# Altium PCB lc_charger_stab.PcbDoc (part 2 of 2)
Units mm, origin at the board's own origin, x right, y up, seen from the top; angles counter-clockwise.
Board outline 145 x 80 mm, 2 copper layers (Top Layer, Bottom Layer), stack 1.562 mm thick; 160 components, 79 nets, 423 pads, 71 vias.
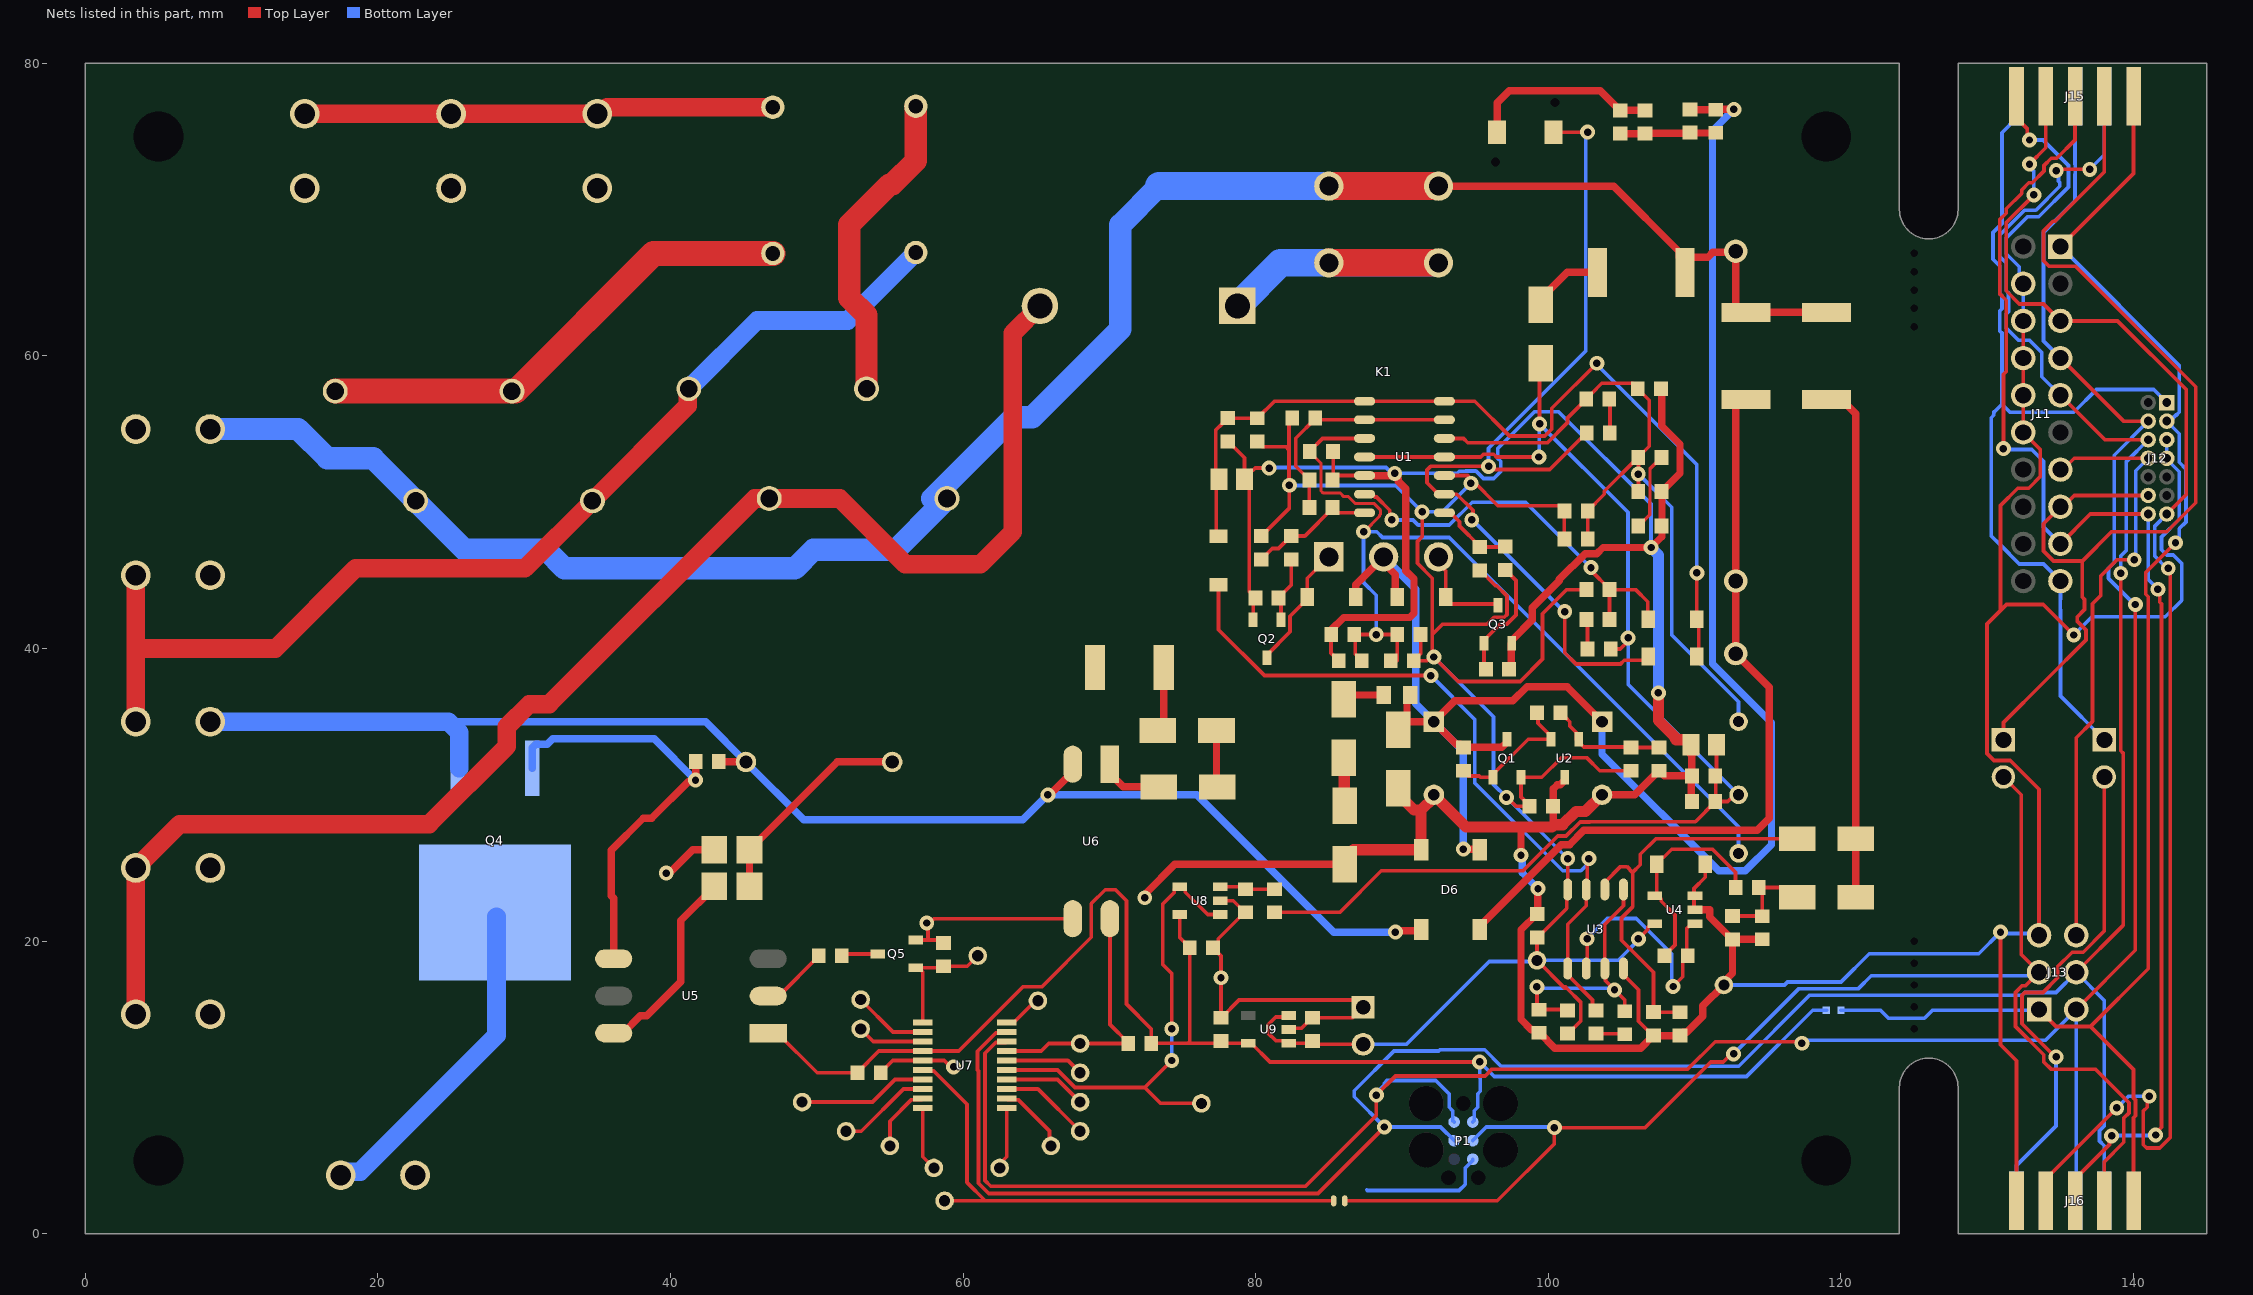
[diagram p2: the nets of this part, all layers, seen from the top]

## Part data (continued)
U9: library part CMP-ICPWR-00007-3, "200mA positive 18VIN 3.3Vout SOT-23-5 Linear Voltage Regulators (LDO) ROHS", Case/Package=SOT-23-5, Max Supply Voltage=18V, Output Current=200mA, Output Voltage=3.3V
Z1 Z6 Z7: library part CMP-NOBOM-00000-13, "Fiducial 1 mm copper, 3 mm solder mask, two footprint options."

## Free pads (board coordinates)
  round 0 hole 0.508 unplated paste-2539.97 mask+0: 2(125,14) 4(125,15.5) 5(125,17) 7(125,20) 8(125,18.5) 9(125,67) 10(125,65.75) 11(125,64.5) 12(125,63.25) 13(125,62)

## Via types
v1: diameter 1.016, hole 0.508, Top Layer to Bottom Layer, tented both sides, 70 vias
v2: diameter 1.6, hole 1, Top Layer to Bottom Layer, 1 vias

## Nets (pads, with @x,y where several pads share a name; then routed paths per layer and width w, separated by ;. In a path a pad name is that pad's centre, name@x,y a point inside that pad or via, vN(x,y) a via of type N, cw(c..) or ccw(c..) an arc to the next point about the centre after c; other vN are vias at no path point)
3V3: C3.1 C4.1 C9.1 NT1.2 P1.1 R30.1 U5.1 U7.4 U8.5 U9.5 | length 105.5
  Top Layer w0.254: U5.1@46.68,13.71 47.315,13.71 50.025,11 C4.1@52.774,11 52.774,11.025 54.239,12.49 U7.4@57.239,12.49 59.702,12.49 64.094,16.882 65.386,16.882 68.765,20.26 68.765,22.562 69.713,23.51 70.417,23.51 71.165,22.762 71.165,15.7 72.865,14 R30.1@72.865,13.012 75.34,13.012 ; U8.5@74.813,21.812 74.813,20.243 75.488,19.568 C3.1@75.488,19.543 75.488,13.16 75.34,13.012 ; v1(95.304,11.741) 80.972,11.741 79.701,13.012 U9.5@79.501,13.012 77.777,13.012 C9.1@77.627,13.162 77.477,13.012 75.34,13.012
  Bottom Layer w0.254: P1.1@94.831,7.635 94.935,7.739 94.935,8.411 95.171,8.647 95.171,9.553 95.352,9.734 95.352,10.615 95.304,10.663 v1(95.304,11.741) 96.295,10.75 113.545,10.75 118.07,15.275 NT1.2@119.007,15.275
5Vprobe: J11.19 J12.1 J15.1 J17.1 | length 62
  Bottom Layer w0.254: 130.445,55.953 130.269,55.777 130.269,47.696 130.898,47.067 132.192,45.773 133.835,45.773 J11.19@135,44.608 135,43.376 134.978,43.354 134.978,42.662 135,42.64 135,36.759 J17.1@138,33.759 ; 130.445,55.957 130.463,56.157 130.537,56.231 131,56.694 ; J15.1@132,77.75 132,76.25 131,75.25 131,69.046 130.39,68.436 130.39,66.611 130.844,66.157 130.844,64.259 131,64.103 131,63.213 130.844,63.057 130.844,61.719 131,61.563 131,56.694 ; J12.1@142.27,56.81 141.385,57.695 137.456,57.695 135.907,56.146 131.548,56.146 131,56.694
5Vtarget: J16.1 J17.2 | length 34.6
  Top Layer w0.254: v1(134.7,12.087) 134.647,12.087 132.376,14.357 132.376,16.298 132.568,16.49 133.803,16.49 134.808,17.494 134.808,18.241 135.813,19.246 136.559,19.246 138,20.686 J17.2@138,31.219
  Bottom Layer w0.254: J16.1@132,2.25 132,4.669 134.7,7.369 v1(134.7,12.087)
ac_sense: SNS.1 U7.15 U8.1 U8.4 | length 33.2
  Top Layer w0.254: U7.15@62.989,11.19 66.45,11.19 67.64,10 72.416,10 ; v1(74.256,11.84) 72.416,10 ; v1(74.256,14) 74.256,17.791 73.64,18.407 73.64,22.539 74.44,23.339 74.44,23.539 74.613,23.712 U8.4@74.813,23.712 75.013,23.712 75.186,23.539 75.186,23.339 76.713,21.812 U8.1@77.563,21.812 ; SNS.1@76.288,8.909 73.507,8.909 72.416,10
  Bottom Layer w0.254: v1(74.256,11.84) v1(74.256,14)
diffp: R36.2 R37.1 U8.3 | length 3.8
  Top Layer w0.254: U8.3@77.563,23.712 79.128,23.712 R37.1@79.288,23.552 R36.2@81.288,23.552
gate: Q4.G R33.1 U5.4 | length 30.5
  Top Layer w0.508: U5.4@36.12,18.79 36.12,22.92 35.948,23.092 35.948,26.208 38.152,28.412 38.73,28.412 41.221,30.903 41.612,30.903 v1(41.709,31) 41.714,31.005 41.714,32.272 R33.1@41.719,32.277
  Bottom Layer w0.508: Q4.G@30.54,31.815 30.54,33.215 30.786,33.461 31.584,33.461 31.952,33.829 38.88,33.829 v1(41.709,31)
GND: GDT2.2 J7.1 J7.2 J8.1 J8.2 J9.1 J9.2 | length 32.2
  Top Layer w1.27: J8.1@15,76.54 J7.1@25,76.54 J9.1@35,76.54 35.206,76.54 35.666,77 GDT2.2@47,77
GND_PROT: C1.2 C3.2 C4.2 C8.2 C9.2 C12.2 C15.2 C16.2 C25.2 C119.2 C120.2 C121.2 C122.2 C123.2 C124.- C125.- D6.- D8.A D20.A D22.A J10.1 J11.4 J11.6 J11.8 J11.10 J11.12 J12.5 J12.7 J13.5 J15.6 J16.6 P1.5 Q2.2 Q3.2 Q5.2 R6.2 R9.2 R15.2 R17.1 R21.2 R24.1 R28.2 R31.2 R35.2 R37.2 R39.2 R44.2 R47.2 R64.2 TP12.1 U1.12 U2.3 U3.4 U4.2 U4.3 U6.3 U7.5 U8.2 U9.2 | length 409.4
  Top Layer w0.229: C120.2@107.673,57.749 C120.2@107.762,57.66
  Top Layer w0.254: C4.2@54.374,11 54.374,11.025 55.189,11.84 U7.5@57.239,11.84 58.708,11.84 59.143,11.405 v1(59.349,11.405) ; Q5.2@56.754,20.072 57.603,20.072 ; R35.2@58.657,19.867 58.451,20.072 57.603,20.072 ; U6.3@67.495,21.53 58.016,21.53 57.722,21.237 v1(57.516,21.237) 57.603,21.15 57.603,20.072 ; U8.2@77.563,22.762 78.458,22.762 R37.2@79.248,21.972 ; C9.2@77.627,14.762 v1@77.627,17.561 ; v1(77.627,17.5) v1@77.627,17.561 ; C9.2@77.652,14.762 78.861,15.972 86.854,15.972 J10.1@87.337,15.489 86.609,14.762 C8.2@83.876,14.762 83.851,14.762 83.132,14.043 82.332,14.043 U9.2@82.251,13.962 ; C122.2@78.098,54.145 78.123,54.145 79.229,53.04 C1.2@79.229,51.577 ; R37.2@79.288,21.972 R37.2@79.248,21.972 ; C1.2@79.306,51.81 79.682,52.185 79.837,52.185 79.982,52.33 v1(80.909,52.33) ; C1.2@79.562,51.04 79.562,43.893 79.822,43.632 Q2.2@79.822,41.654 ; R28.2@85.149,40.954 85.149,39.697 85.657,39.189 R31.2@85.657,39.164 ; R9.2@85.265,51.504 R9.2@85.293,51.531 ; C121.2@85.293,53.462 R9.2@85.293,51.531 ; U1.12@88.133,51.82 U1.12@87.44,51.82 85.581,51.82 R9.2@85.293,51.531 ; U3.4@105.133,18.124 105.133,17.694 106.157,16.67 106.157,14.526 C16.2@106.788,13.895 ; R15.2@107.767,50.408 R15.2@107.767,50.75 ; U4.2@109.951,22.144 109.951,23.593 110.725,24.367 D20.A@110.725,25.253 ; v1(130.901,20.619) 130.901,12.92 132,11.821 J16.6@132,2.25 ; J15.6@132,77.75 132,76.25 132.74,75.51 132.74,74.901 v1(132.886,74.755) ; J11.6@132.46,62.388 J11.8@132.46,59.848 J11.10@132.46,57.308 J11.12@132.46,54.768 133.622,53.606 133.622,51.747 132.833,50.958 132.087,50.958 130.901,49.773 130.901,42.593 ; J13.5@133.538,20.408 133.538,30.379 131.571,32.346 130.454,32.346 129.977,32.824 129.977,41.668 130.901,42.593 ; v1(135.907,40.921) 133.821,43.008 131.317,43.008 130.901,42.593 ; v1@77.627,17.561 77.627,18.98 77.088,19.518 C3.2@77.088,19.543 77.436,19.891 77.436,20.16 R37.2@79.248,21.972
  Top Layer w0.508: v1(72.416,22.962) 72.513,23.059 72.513,23.287 74.478,25.252 D8.A@86.087,25.252 ; R28.2@85.134,41.235 86.018,42.119 90.518,42.119 90.816,42.417 90.816,44.755 90.267,45.304 90.267,50.905 89.742,51.43 ; U1.12@88.133,51.82 89.52,51.82 v1@89.742,51.597 ; R24.1@97.325,38.579 97.455,38.71 97.455,40.315 97.547,40.407 97.547,40.607 98.896,41.956 98.896,42.772 100.751,44.626 100.751,44.723 102.514,46.487 103.316,46.487 103.734,46.904 v1(107.019,46.904) 107.767,47.652 R15.2@107.767,50.408 ; 97.98,27.799 98.133,27.646 v1(98.133,25.873) ; v1(99.291,23.593) 99.269,23.571 99.269,21.875 C25.2@99.247,21.853 99.222,21.853 98.133,20.763 98.133,14.653 98.834,13.952 99.158,13.952 R64.2@99.374,13.735 ; R64.2@99.399,13.726 100.435,12.69 106.303,12.69 107.161,13.547 C16.2@107.186,13.547 107.189,13.544 R47.2@109.005,13.544 ; 100.175,27.799 100.325,27.949 C119.2@100.325,29.225 100.325,30.4 100.622,30.698 100.822,30.698 101.125,31 U2.3@101.125,31.2 ; C124.-@103.669,30 105.894,30 107.534,31.64 107.584,31.64 107.929,31.295 R44.2@109.765,31.295 ; C120.2@107.762,57.66 107.762,55.209 108.999,53.972 108.999,51.982 R15.2@107.767,50.75 ; R47.2@109.008,13.551 109.224,13.767 109.458,13.767 110.561,14.87 110.561,15.572 112.014,17.025 112.014,17.231 112.588,17.806 C12.2@112.588,20.113 ; C15.2@109.765,29.617 R44.2@109.765,31.295 ; C123.2@109.791,32.899 R44.2@109.791,31.295 ; R44.2@109.816,31.295 R44.2@109.791,31.295 ; U4.2@109.951,22.144 U4.2@110.026,22.144 111.031,22.144 111.031,21.646 112.563,20.113 C12.2@112.588,20.113 ; R39.2@114.62,20.113 C12.2@112.588,20.113 ; R44.2@109.765,31.295 R44.2@109.791,31.295
  Top Layer w0.762: D8.A@86.087,25.252 86.087,25.652 86.684,26.249 D6.-@91.304,26.249 91.304,28.957 ; D22.A@89.743,30.44 89.743,30.04 90.826,28.957 91.304,28.957 ; C124.-@103.669,30 102.523,28.854 101.881,28.854 100.982,27.955 100.412,27.955 100.256,27.799 100.175,27.799 97.98,27.799 94.376,27.799 C125.-@92.175,30 92.175,29.827 91.304,28.957 ; v1(107.526,36.965) 107.526,35.07 108.651,33.945 108.651,33.844 108.731,33.763 109.542,33.763 109.741,33.564 C123.2@109.741,33.409 ; C123.2@109.791,32.899 C123.2@109.791,33.409
  Bottom Layer w0.254: v1@80.909,52.372 88.899,52.372 89.299,51.972 v1(89.505,51.972) 93.773,51.972 93.923,52.122 94.345,52.122 94.356,52.133 95.047,52.133 95.569,51.612 96.261,51.612 96.75,52.101 96.75,52.793 96.55,52.992 96.55,53.68 99.056,56.187 100.701,56.187 107.019,49.869 v1(107.019,46.904) ; 87.587,3 87.634,2.953 92.812,2.953 92.816,2.948 93.543,2.948 93.548,2.953 93.898,2.953 94.32,3.374 94.32,4.501 94.831,5.012 P1.5@94.831,5.095 ; TP12.1@112,17 116.136,17 116.342,17.206 120.008,17.206 121.933,19.131 129.414,19.131 v1(130.901,20.619) 131.007,20.513 133.433,20.513 J13.5@133.538,20.408 ; J11.6@132.46,62.388 J11.4@132.46,64.928 132.189,65.199 132.189,66.096 131.298,66.987 131.298,68.06 132.74,69.502 133.51,69.502 135.546,71.538 135.546,72.582 135.55,72.586 135.55,73.011 133.806,74.755 v1(132.886,74.755) ; v1(135.907,40.921) 137.151,42.165 142.169,42.165 143.292,43.289 143.292,45.803 142.707,46.388 142.267,46.388 141.908,46.747 141.908,47.616 143.127,48.835 143.127,52.085 142.27,52.942 J12.7@142.27,53 J12.5@142.27,54.27
  Bottom Layer w0.508: v1(98.133,25.873) 98.23,25.776 98.23,24.654 v1(99.291,23.593)
  Bottom Layer w0.762: v1(107.019,46.904) 107.526,46.397 v1(107.526,36.965)
heater_out: J2.1 J2.2 MECH2.1 Q4.OUT R22.2 | length 26.8
  Top Layer w0.508: v1(39.71,24.65) 39.807,24.747 40.026,24.747 41.529,26.25 R22.2@42.98,26.25
  Bottom Layer w1.27: J2.1@17.46,3.75 17.96,4.25 18.79,4.25 28.11,13.57 Q4.OUT@28.11,21.675
input_ok: C1.1 C122.1 D3.A D4.A D5.A R5.2 U1.7 U1.8 | length 61.7
  Top Layer w0.254: C1.1@77.302,51.577 77.302,47.82 D4.A@77.454,47.668 ; C1.1@77.479,51.577 77.272,51.785 77.272,54.927 77.726,55.381 77.726,55.397 78.074,55.745 R5.2@79.953,55.745 ; R5.2@80.105,55.745 80.13,55.745 81.284,56.9 U1.8@87.44,56.9 U1.7@92.565,56.9 ; U1.7@92.89,56.9 94.969,56.9 97.352,54.517 99.748,54.517 100.237,55.006 100.237,56.419 v1(103.319,59.5) ; D5.A@110.262,39.2 110.287,39.2 110.287,41.858 D3.A@110.151,41.994 v1(110.151,45.169) ; v1(110.151,45.169) 110.151,45.236 110.036,45.351 110.002,45.318 109.853,45.169 v1(110.151,45.169)
  Bottom Layer w0.254: v1(103.319,59.5) 103.319,59.39 110.151,52.558 v1(110.151,45.169)
L2: J1.1 J1.2 J3.1 J3.2 L2.2 R1.1 RV2.1 | length 100.3
  Top Layer w1.27: J1.2@3.46,15 J3.2@3.46,25 6.46,28 23.5,28 28.808,33.308 28.808,34.651 30.357,36.2 31.7,36.2 45.75,50.25 RV2.1@46.75,50.25 51.57,50.25 56.055,45.765 61.185,45.765 63.385,47.965 63.385,61.549 L2.2@65.25,63.414
  Bottom Layer w1.27: L2.2@65.25,63.373 L2.2@65.25,63.414 L2.2@65.25,63.499
LINE: C5.1 J4.1 J4.2 K1.NO1 K1.NO2 R2.1 R3.1 R10.1 RV1.2 RV3.1 | length 145.2
  Top Layer w0.508: K1.NO2@92.493,71.602 104.463,71.602 108.929,67.136 108.929,66.735 R3.1@109.325,66.339 ; R3.1@109.325,65.697 R3.1@109.325,66.339 ; R10.1@119,62.975 R2.1@113.5,62.975 113.205,62.975 112.809,63.371 C5.1@112.809,67.15 112.731,67.072 111.247,67.072 110.91,66.735 109.721,66.735 R3.1@109.325,66.339
  Top Layer w1.905: K1.NO1@84.993,71.602 K1.NO2@92.493,71.602
  Bottom Layer w1.524: J4.1@8.54,55 14.543,55 16.543,53 19.675,53 RV3.1@22.587,50.088 25.925,46.75 31.48,46.75 32.754,45.476 48.498,45.476 49.772,46.75 55.4,46.75 58.4,49.75 RV1.2@58.9,50.25 ; 57.9,50.25 58.4,50.75 63.461,55.811 64.735,55.811 70.75,61.826 70.75,68.956 73.396,71.602
  Bottom Layer w1.905: 73.396,71.602 K1.NO1@84.993,71.602 K1.NO2@92.493,71.602
LPROT: K1.COM1 K1.COM2 L2.1 | length 22.5
  Top Layer w1.905: K1.COM1@84.975,66.38 K1.COM1@84.993,66.362 K1.COM2@92.493,66.362
  Bottom Layer w1.905: L2.1@78.75,63.414 81.698,66.362 K1.COM1@84.993,66.362 K1.COM2@92.493,66.362
NC.MOV5: GDT2.1 RV3.2 RV4.2 | length 33.8
  Top Layer w1.7: RV3.2@17.087,57.588 29.424,57.588 38.836,67 GDT2.1@47,67
NetC2_1: C2.1 R14.2 R22.1 | length 14.8
  Top Layer w0.508: R14.2@45.4,23.75 R22.1@45.4,26.25 45.4,26.31 46.021,26.931 46.081,26.931 51.395,32.245 C2.1@55.155,32.245
NetC5_2: C5.2 D6.AC1 R2.2 | length 53.1
  Top Layer w0.508: D6.AC1@95.304,20.799 95.304,21.024 100.879,26.599 101.449,26.599 102.415,27.565 107.098,27.565 107.114,27.581 114.281,27.581 115.1,28.4 115.1,37.359 C5.2@112.809,39.65 v2(112.809,44.616) 112.809,56.629 113.205,57.025 R2.2@113.5,57.025
NetC6_2: C6.2 Q2.1 R17.2 | length 4.9
  Top Layer w0.254: Q2.1@81.722,41.654 81.722,43.307 81.572,43.457 81.572,43.482 82.421,44.331 C6.2@82.421,46.092 C6.2@82.446,46.092
NetC7_2: C7.2 Q3.1 R24.2 | length 8.3
  Top Layer w0.254: R24.2@95.725,38.579 95.601,38.703 Q3.1@95.601,40.361 95.601,40.561 96.72,41.68 97.175,41.68 97.787,42.292 97.787,44.646 97.438,44.995 97.438,45.02 97.09,45.368 C7.2@97.065,45.368
NetC118_1: C118.1 Q1.1 R20.1 U2.2 | length 9.6
  Top Layer w0.254: R20.1@94.196,31.64 94.544,31.292 95.264,31.292 95.356,31.2 Q1.1@96.225,31.2 96.225,31.4 98.624,33.8 U2.2@100.175,33.8 100.175,34 99.287,34.888 99.287,35.567 C118.1@99.234,35.62
NetC118_2: C118.2 R6.1 R13.2 U2.1 | length 8.2
  Top Layer w0.254: C118.2@100.834,35.62 100.834,35.595 101.182,35.247 101.207,35.247 101.456,34.997 101.456,34.707 101.902,34.261 101.902,33.773 102.415,33.26 105.631,33.26 105.652,33.24 R6.1@107.559,33.24
NetD7_A: D7.A R1.2 | length 4.5
  Top Layer w0.508: D7.A@73.316,34.4 73.715,34.799 R1.2@73.715,38.703
NetD7_K: D7.K D10.K | length 3.9
  Top Layer w0.508: D7.K@77.316,34.4 77.316,30.594 D10.K@77.365,30.545
NetD8_K: D8.K D9.A | length 3.3
  Top Layer w0.762: D9.A@86.013,32.524 86.05,32.487 86.05,29.289 D8.K@86.087,29.252
NetD9_K: D9.K R181.2 | length 2.9
  Top Layer w0.508: D9.K@86.013,36.524 86.311,36.821 R181.2@88.76,36.821
NetD10_A: D10.A U6.1 | length 4.3
  Top Layer w0.508: U6.1@70.035,32.09 70.035,31.455 70.945,30.545 D10.A@73.365,30.545
NetD20_K: D20.K R50.2 R59.1 U4.4 | length 15.2
  Top Layer w0.254: R59.1@107.643,18.708 107.935,19 107.935,19.025 108.651,19.74 108.651,21.319 108.651,21.794 107.724,22.721 107.724,22.871 107.501,23.094 107.351,23.094 107.405,23.148 D20.K@107.405,25.253 107.405,25.405 107.736,25.735 107.888,25.735 108.439,26.286 111.221,26.286 112.795,24.712 R50.2@112.795,23.669
NetD57_A: D57.A R3.2 | length 5
  Top Layer w0.254: D57.A@99.477,63.5 D57.A@99.477,63.9
  Top Layer w0.508: D57.A@99.477,63.9 101.295,65.718 R3.2@103.354,65.718
NetD58_A: D58.A D59.K R10.2 | length 35.5
  Top Layer w0.508: R10.2@119,57.025 120.025,57.025 120.421,56.629 121,56.05 D59.K@121,23
NetD60_A: D60.A R48.2 R49.2 | length 13
  Top Layer w0.508: D60.A@96.498,75.292 96.498,77.292 97.339,78.133 103.547,78.133 104.89,76.789 104.915,76.789 R49.2@106.6,76.789
NetGDT1_2: GDT1.2 RV1.1 | length 21.8
  Top Layer w1.524: RV1.1@53.4,57.75 53.4,62.782 52.21,63.972 52.21,68.956 54.97,71.716 55.15,71.716 56.772,73.338 GDT1.2@56.772,77.067
NetQ5_3: Q5.3 R34.2 | length 2.5
  Top Layer w0.254: R34.2@51.705,19 51.827,19.122 Q5.3@54.154,19.122
NetR4_1: R4.1 R8.1 | length 2.3
  Top Layer w0.254: R4.1@104.179,57.019 R4.1@104.179,57.044 ; R8.1@104.211,54.742 R4.1@104.211,57.044
NetR7_2: R7.2 R9.1 R12.1 U1.6 U1.9 | length 16
  Top Layer w0.254: R12.1@83.665,49.624 83.665,51.504 83.665,51.529 82.732,52.462 82.732,54.371 84.081,55.72 84.081,55.745 84.197,55.63 U1.6@92.959,55.63
NetR11_1: R11.1 R21.1 | length 5.2
  Top Layer w0.203: 106.936,50.067 106.936,51.547 106.956,51.567 106.956,52.283
  Top Layer w0.254: R21.1@106.167,48.376 106.936,49.145 106.936,50.067 ; 106.956,52.283 R11.1@107.622,52.948
NetR14_1: R14.1 U5.6 | length 13.5
  Top Layer w0.508: U5.6@36.12,13.71 36.755,13.71 37.946,14.901 38.366,14.901 40.7,17.235 40.7,21.41 42.98,23.69 R14.1@42.98,23.75
NetR26_1: R26.1 R27.2 | length 2.1
  Top Layer w0.254: R26.1@102.597,41.993 102.673,41.916 R27.2@102.673,39.961
NetR48_1: R48.1 R49.1 R52.2 R56.2 | length 6.6
  Top Layer w0.508: R48.1@104.915,75.189 106.6,75.189 106.631,75.22 109.649,75.22 R56.2@109.679,75.25 ; R56.2@109.68,75.235 R52.2@111.443,75.235
NetR54_1: R54.1 R58.1 | length 2.1
  Top Layer w0.254: R58.1@103.133,13.675 R58.1@103.189,13.619 ; R58.1@103.267,13.675 105.165,13.675 R54.1@105.221,13.619
NEUT: C2.2 D6.AC2 GDT1.1 J5.1 J5.2 J6.1 J6.2 Q4.COM R33.2 RV2.2 RV4.1 U6.2 | length 173.6
  Top Layer w0.508: R33.2@43.299,32.277 43.315,32.261 45.139,32.261 C2.2@45.155,32.245 ; v1(65.79,29.996) 65.913,29.996 67.495,31.578 U6.2@67.495,32.09 ; v1(89.542,20.619) 89.632,20.709 91.214,20.709 D6.AC2@91.304,20.799
  Top Layer w1.27: J5.2@3.46,35 3.46,40 ; J6.2@3.46,45 3.46,40 ; RV2.2@41.25,57.75 41.168,57.668 41.168,56.591 RV4.1@34.664,50.088 30.052,45.476 18.476,45.476 13,40 3.46,40
  Bottom Layer w0.508: 24.826,35 42.4,35 C2.2@45.155,32.245 49.109,28.291 64.086,28.291 v1(65.79,29.996) 75.96,29.996 85.337,20.619 v1(89.542,20.619)
  Bottom Layer w1.27: J5.1@8.54,35 24.826,35 25.57,34.256 Q4.COM@25.57,31.815 ; RV2.2@41.25,57.75 45.918,62.418 52.123,62.418 GDT1.1@56.772,67.067
NRST: J13.3 J14.2 J16.9 P1.3 SJ1.1 | length 97
  Top Layer w0.254: SJ1.1@86.087,2.25 96.512,2.25 100.412,6.15 v1(100.412,7.25) 106.614,7.25 111.105,11.741 111.952,11.741 112.5,12.289 v1(112.661,12.289) ; J14.2@131.104,31.219 132.314,30.009 132.314,19.092 J13.3@133.538,17.868 132.614,16.944 132.38,16.944 131.922,16.486 131.922,14.169 133.865,12.226 133.865,11.741 134.354,11.252 137.375,11.252 139.681,8.946 139.681,8.254 139.335,7.908 139.335,6.246 138,4.911 J16.9@138,2.25
  Bottom Layer w0.254: P1.3@94.831,6.365 95.76,7.295 100.367,7.295 v1(100.412,7.25) ; v1(112.661,12.289) 117.125,16.752 121.193,16.752 122.072,17.631 133.301,17.631 J13.3@133.538,17.868
NRST_MCU: NRST_MCU.1 SJ1.2 U7.6 | length 37.7
  Top Layer w0.254: U7.6@57.239,11.19 57.312,11.117 58,11.117 60.26,8.857 60.26,3.51 61.52,2.25 ; NRST_MCU.1@58.739,2.25 61.52,2.25 ; SJ1.2@85.325,2.25 61.52,2.25
NRST_PROBE: J11.15 J12.12 J14.1 J15.9 | length 72.2
  Top Layer w0.254: J14.1@131.104,33.759 131.104,34.94 133.921,37.758 133.925,37.758 136.742,40.576 136.742,41.267 136.159,41.851 136.159,42.173 136.648,42.662 136.648,43.354 136.5,43.502 136.5,45.986 ; J15.9@138,77.75 138,72.569 134.631,69.2 134.5,69.2 133.838,68.538 133.838,66.498 134.202,66.134 136.011,66.134 144.25,57.894 144.25,49.958 142.264,47.972 138.486,47.972 136.5,45.986 ; J12.12@141,50.46 135.948,50.46 135.176,49.688 J11.15@135,49.688 133.838,48.526 133.838,46.667 134.519,45.986 136.5,45.986
opto_k1: R34.1 U5.2 | length 4.6
  Top Layer w0.254: U5.2@46.68,16.25 47.415,16.25 50.125,18.96 R34.1@50.125,19
overvoltage#: D5.K D60.K R8.2 U1.2 | length 63.2
  Top Layer w0.254: U1.2@92.565,50.55 92.484,50.55 91.712,51.322 91.712,52.205 91.953,52.447 v1(95.915,52.447) 96.134,52.227 100.096,52.227 102.238,54.369 102.263,54.369 102.611,54.717 R8.2@102.611,54.742 ; U1.2@92.959,50.55 93.74,50.55 94.843,49.447 94.843,48.864 v1(94.768,48.788) ; D60.K@100.361,75.292 v1(102.679,75.292) ; v1(101.125,42.524) 101.125,39.708 101.887,38.946 104.935,38.946 105.189,39.2 106.812,39.2 D5.K@106.694,39.317
  Bottom Layer w0.254: v1(94.768,48.788) 94.814,48.788 101.078,42.524 v1(101.125,42.524) ; v1(95.915,52.447) 95.915,53.687 102.562,60.335 102.562,75.175 v1(102.679,75.292)
PA0: PA0.1 U7.7 | length 8.9
  Top Layer w0.254: PA0.1@49,9 53.811,9 55.351,10.54 U7.7@57.239,10.54
PA1: PA1.1 U7.8 | length 6.4
  Top Layer w0.254: PA1.1@52,7 53.038,7 55.928,9.89 U7.8@57.239,9.89
PA2: PA2.1 U7.9 | length 4.6
  Top Layer w0.254: PA2.1@55,6 55,7.688 56.479,9.167 57.166,9.167 U7.9@57.239,9.24
PA3: PA3.1 U7.10 | length 4.4
  Top Layer w0.254: U7.10@57.239,8.59 57.239,5.261 PA3.1@58,4.5
PA4: PA4.1 U7.11 | length 4.3
  Top Layer w0.254: PA4.1@62.5,4.5 62.5,4.775 62.989,5.264 U7.11@62.989,8.59
PA5: PA5.1 U7.12 | length 4.9
  Top Layer w0.254: U7.12@62.989,9.24 63.062,9.167 63.75,9.167 65.901,7.016 65.901,6.099 PA5.1@66,6
PA6: PA6.1 U7.13 | length 6.2
  Top Layer w0.254: U7.13@62.989,9.89 65.11,9.89 PA6.1@68,7
PA7: PA7.1 U7.14 | length 5.6
  Top Layer w0.254: U7.14@62.989,10.54 66.457,10.54 67.997,9 PA7.1@68,9
PA11: PA11.1 U7.16 | length 5.4
  Top Layer w0.254: U7.16@62.989,11.84 67.16,11.84 PA11.1@68,11
PB6: PB6.1 U7.20 | length 2.7
  Top Layer w0.254: U7.20@62.989,14.44 63.464,14.44 64.944,15.92 PB6.1@65.114,15.92
PC14: PC14.1 U7.2 | length 5.2
  Top Layer w0.254: PC14.1@53,16 55.21,13.79 U7.2@57.239,13.79
PC15: PC15.1 U7.3 | length 4.6
  Top Layer w0.254: PC15.1@53,14 53.86,13.14 U7.3@57.239,13.14
peak_neg: C12.1 D59.A R39.1 R50.1 | length 7
  Top Layer w0.254: C12.1@112.563,21.713 114.62,21.713 114.62,23.443 114.395,23.669 116.331,23.669 D59.A@117,23
peak_neg_inv: R59.2 U3.2 U4.1 | length 16.1
  Top Layer w0.254: v1(102.651,20.159) 102.655,20.155 102.655,18.009 U3.2@102.658,18.005 ; v1(108.524,16.898) 109.187,17.562 109.187,18.652 R59.2@109.535,19 ; R59.2@109.451,19.323 109.451,20.844 109.801,21.194 U4.1@109.951,21.194
  Bottom Layer w0.254: v1(102.651,20.159) 104.044,21.553 106.003,21.553 ; 106.02,21.534 108.248,19.307 108.439,19.116 v1@108.439,17.221
peak_out: D4.K R58.2 U3.1 U3.7 | length 49.1
  Top Layer w0.254: D4.K@77.454,44.348 77.454,41.288 80.592,38.15 v1(91.97,38.15) ; U3.1@101.323,18.424 101.323,21.154 102.593,22.424 U3.7@102.593,23.224 ; U3.1@101.388,18.005 101.436,17.957 101.436,17.561 103.015,15.982 103.015,15.527 R58.2@103.107,15.435 ; U3.7@102.593,23.524 102.659,23.59 102.659,25.529 v1(102.767,25.637)
  Bottom Layer w0.254: v1(91.97,38.15) 94.97,35.15 94.97,30.809 100.977,24.802 102.223,24.802 102.762,25.341 102.762,25.632 v1(102.767,25.637)
peak_pos: C16.1 D58.K R47.1 U3.6 | length 28.2
  Top Layer w0.254: U3.6@103.863,23.524 103.863,24.024 104.93,25.091 105.367,25.091 105.76,24.698 ; C16.1@106.97,15.147 C16.1@106.976,15.141 ; R47.1@109.002,15.147 C16.1@107.186,15.147 107.186,17.868 104.993,20.06 104.993,21.572 105.76,22.339 105.76,24.698 ; D58.K@117,27 107.355,27 106.286,25.932 106.286,25.224 105.76,24.698
peak_thresh: R54.2 R62.2 R64.1 U3.3 U3.5 | length 17.4
  Top Layer w0.254: R64.1@99.222,15.478 v1(99.222,16.868) ; R64.1@99.241,15.325 R64.1@99.291,15.275 ; R64.1@99.374,15.325 R62.2@101.273,15.325 ; U3.3@103.863,18.424 103.863,21.154 105.133,22.424 U3.5@105.133,23.224 ; U3.3@103.864,17.941 103.909,17.896 103.909,17.284 v1(104.523,16.67) 105.221,15.972 R54.2@105.221,15.219
  Bottom Layer w0.254: v1(99.222,16.868) 99.321,16.769 104.424,16.769 v1(104.523,16.67)
PROT_RESET: D1.A K1.RESET Q2.3 | length 8.6
  Top Layer w0.254: Q2.3@80.772,39.363 80.772,39.563 82.349,41.14 82.349,42.196 83.527,43.374 D1.A@83.527,43.526 83.527,44.796 K1.RESET@84.993,46.262
PROT_SET: D2.A K1.SET Q3.3 | length 6.8
  Top Layer w0.254: K1.SET@92.493,46.262 92.493,45.805 92.98,45.318 92.98,43.372 93.31,43.042 96.47,43.042 Q3.3@96.551,42.961
ref_high: C120.1 R4.2 R11.2 R15.1 R19.2 R23.2 TP9.1 U1.5 | length 50.2
  Top Layer w0.254: U1.5@92.89,54.36 94.196,54.36 94.492,54.063 99.936,54.063 101.311,55.437 101.311,55.751 102.579,57.019 102.579,57.044 102.579,57.069 102.927,57.417 102.952,57.417 103.656,58.122 105.763,58.122 106.111,57.774 C120.1@106.111,57.749 106.891,56.969 106.891,53.817 106.136,53.062 103.824,50.75 103.824,50.542 102.687,49.404 102.698,49.393 102.698,49.391 R23.2@102.698,47.486 ; v1(106.147,51.923) v1@106.167,51.923 ; R15.1@106.167,50.408 v1@106.167,51.923 ; R11.2@106.37,52.948 106.167,52.745 v1@106.167,51.923
  Bottom Layer w0.254: v1(106.147,51.923) 106.167,51.923 108.439,49.65 108.439,40.921 113,36.36 TP9.1@113,35
ref_low: C121.1 R28.1 R29.2 R31.1 R32.2 TP13.1 U1.10 | length 63.6
  Top Layer w0.203: C121.1@83.693,53.462 83.693,53.437 84.465,52.665 84.465,50.757 84.584,50.638 85.751,50.638 86.015,50.374 86.34,50.374 86.788,49.926 88.07,49.926 88.518,49.478 88.518,49.173 88.467,49.122 88.467,49.03 87.415,47.979 v1(87.371,47.979)
  Top Layer w0.254: C121.1@83.693,53.462 83.693,53.487 84.565,54.36 U1.10@87.44,54.36 ; R31.1@87.257,39.164 86.8,39.621 86.8,40.954 v1(88.235,40.954) 89.67,40.954 R32.2@89.67,39.164
  Bottom Layer w0.254: v1(88.235,40.954) 88.235,43.645 87.371,44.509 v1(87.371,47.979) 88.269,47.979 88.659,47.589 93.224,47.589 113,27.813 TP13.1@113,26
reset: C6.1 R12.2 R16.2 U1.14 | length 8.7
  Top Layer w0.254: R16.2@80.389,46.092 81.132,46.835 81.564,46.835 C6.1@82.421,47.692 83.358,47.692 85.265,49.599 85.265,49.624 85.61,49.28 U1.14@87.44,49.28
sense_prot: C15.1 C123.1 D57.K R27.1 R36.1 R44.1 TP16.1 U1.4 U1.11 | length 89.6
  Top Layer w0.254: R36.1@81.288,21.972 85.755,21.972 88.585,24.802 98.26,24.802 100.638,27.18 101.208,27.18 102.174,28.146 102.816,28.146 102.832,28.162 110.049,28.162 111.43,29.543 C15.1@111.441,29.543 ; U1.11@87.371,53.09 U1.4@92.565,53.09 ; U1.4@92.959,53.09 95.377,53.09 95.569,53.282 96.261,53.282 96.453,53.09 v1(99.35,53.09) ; v1(99.402,55.352) 99.402,59.425 D57.K@99.477,59.5 ; R27.1@104.273,39.961 104.921,39.961 105.454,40.494 v1(105.454,40.723) ; R44.1@111.441,31.067 C15.1@111.441,29.543 ; R44.1@111.466,31.295 111.416,31.295 111.491,31.37 C123.1@111.491,33.409 ; TP16.1@113,30 112.725,30 112.268,29.543 C15.1@111.441,29.543
  Bottom Layer w0.254: v1(99.35,53.09) 99.376,53.116 99.376,55.326 v1(99.402,55.352) 105.443,49.312 v1@105.443,40.723 ; v1(105.454,40.723) 105.454,37.546 TP16.1@113,30
set: C7.1 R18.2 U1.1 | length 5.3
  Top Layer w0.254: U1.1@92.89,49.28 93.315,49.28 93.933,48.662 93.933,48.374 R18.2@95.313,46.994 ; R18.2@95.313,46.943 97.04,46.943 C7.1@97.065,46.968
SWDCLK: J11.9 J12.6 J13.4 J15.4 J16.4 P1.4 U7.19 | length 193.8
  Top Layer w0.254: U7.19@62.989,13.79 62.916,13.717 62.229,13.717 60.99,12.478 60.99,11.19 61.046,11.134 61.046,3.451 61.747,2.75 84.25,2.75 v1(88.795,7.295) ; v1(134.715,72.665) 134.8,72.75 v1(137,72.75) ; J11.9@135,57.308 138.038,54.27 J12.6@141,54.27 ; J13.4@136.078,17.868 139.285,21.075 139.285,32.852 139.127,33.01 139.127,45.13 v1(139.119,45.138)
  Bottom Layer w0.254: P1.4@93.561,6.365 92.631,7.295 v1(88.795,7.295) 86.73,9.359 86.73,9.772 89.453,12.495 92.511,12.495 92.592,12.576 95.65,12.576 96.772,11.454 113.007,11.454 117.851,16.298 132.376,16.298 132.568,16.49 134.7,16.49 J13.4@136.078,17.868 138,15.946 138,7.369 137.665,7.034 137.665,6.342 138,6.007 J16.4@138,2.25 ; v1(134.715,72.665) 134.861,72.519 134.861,71.937 134.955,71.843 134.955,71.589 133.322,69.956 132.552,69.956 130.844,68.248 130.844,66.799 131.298,66.345 131.298,64.447 131.454,64.291 131.454,63.025 131.298,62.869 131.298,61.907 132.139,61.065 132.886,61.065 133.727,60.224 133.727,58.581 J11.9@135,57.308 ; v1(137,72.75) 138,73.75 J15.4@138,77.75 ; v1(139.119,45.138) 139.126,45.146 139.126,46.327 139.507,46.708 139.507,52.777 J12.6@141,54.27
SWDIO: J11.7 J12.4 J13.2 J15.3 J16.3 P1.2 U7.18 | length 183.8
  Top Layer w0.254: U7.18@62.989,13.14 62.916,13.067 62.229,13.067 61.5,12.338 61.5,3.64 61.89,3.25 83.407,3.25 88.243,8.086 v1(88.243,9.476) 89.554,10.787 95.687,10.787 96.15,11.251 109.531,11.251 111.405,13.124 117.223,13.124 v1(117.325,13.022) ; J11.7@135,59.848 139.308,55.54 J12.4@141,55.54 ; J13.2@136.078,15.328 140.12,19.37 v1(140.12,43.008)
  Bottom Layer w0.254: v1(88.243,9.476) 88.243,9.63 88.795,10.182 88.795,10.287 88.977,10.47 92.304,10.47 93.22,9.553 93.22,8.647 93.456,8.411 93.456,7.739 P1.2@93.561,7.635 ; v1(117.325,13.022) 117.203,13.022 116.999,13.226 133.976,13.226 J13.2@136.078,15.328 136.078,2.328 J16.3@136,2.25 ; J11.7@135,59.848 133.838,61.01 133.838,68.438 136,70.6 136,72.394 136.011,72.404 136.011,73.096 136,73.106 J15.3@136,77.75 ; v1(140.12,43.008) 140.068,43.008 138.284,44.792 138.284,45.484 138.672,45.873 138.672,53.212 J12.4@141,55.54
SWO: J11.13 J12.8 J13.6 | length 41.6
  Top Layer w0.254: J11.13@135,52.228 135.176,52.228 135.948,53 J12.8@141,53 ; J13.6@136.078,20.408 136.078,33.9 137.196,35.018 137.196,43.062 137.755,43.621 137.755,44.956 138.862,46.063 v1(140.043,46.063)
  Bottom Layer w0.254: v1(140.043,46.063) 140.143,46.163 140.143,52.143 J12.8@141,53
triac_on: Q5.1 R35.1 T_ON.1 U7.1 | length 8.4
  Top Layer w0.254: Q5.1@56.754,18.172 Q5.1@56.954,18.172 ; U7.1@57.239,14.44 57.239,17.887 Q5.1@56.954,18.172 ; T_ON.1@61,19 60.99,19 60.276,18.287 R35.1@58.657,18.287 58.542,18.172 Q5.1@56.954,18.172
undervoltage#: D3.K R25.1 R26.2 U1.13 | length 27.1
  Top Layer w0.254: U1.13@87.371,50.55 87.959,50.55 88.154,50.355 88.247,50.355 89.153,49.449 89.153,48.934 v1(89.299,48.788) ; v1(102.913,45.525) 102.913,45.334 104.197,44.05 104.197,44.025 105.95,44.025 106.787,43.188 106.787,42.375 D3.K@106.812,42.375 ; R25.1@104.173,44.025 104.173,42.017 R26.2@104.197,41.993
  Bottom Layer w0.254: v1(89.299,48.788) 90.744,48.788 91.099,48.433 93.232,48.433 94.797,49.998 98.439,49.998 v1(102.913,45.525)
VCC_PROT: C8.1 C25.1 C119.1 J10.2 Q1.2 R5.1 R7.1 R13.1 R16.1 R18.1 R19.1 R23.1 R25.2 R29.1 R32.1 R62.1 TP15.1 U1.3 U3.8 U4.5 U9.1 U9.3 | length 152.2
  Top Layer w0.254: R5.1@80.105,54.145 80.453,53.797 82.045,53.797 82.278,53.564 ; R16.1@80.389,47.692 80.414,47.692 80.762,48.04 80.762,48.065 82.3,49.603 v1(82.3,51.155) 82.278,51.177 82.278,53.564 ; U9.3@82.251,14.912 82.147,14.807 81.37,14.807 80.876,14.313 80.876,13.685 81.376,13.185 82.078,13.185 U9.1@82.251,13.012 83.726,13.012 C8.1@83.876,13.162 84.089,12.949 J10.2@87.337,12.949 ; R7.1@82.401,55.665 82.278,55.542 82.278,53.564 ; R29.1@91.27,40.954 91.27,39.646 90.813,39.189 90.813,39.164 91.712,39.164 91.966,39.418 v1(92.172,39.418) 93.84,37.75 95.121,37.75 95.129,37.742 97.92,37.742 97.928,37.75 98.077,37.75 99.601,39.274 99.601,42.375 101.251,44.025 R25.2@102.597,44.025 ; R29.1@91.372,40.954 R29.1@91.372,41.03 ; v1(91.372,49.341) 91.372,47.638 91.05,47.316 91.05,45.819 92.071,44.798 92.071,40.954 ; v1@92.071,39.704 92.071,40.954 ; U1.3@92.959,51.82 94.483,51.82 v1@94.864,51.439 ; v1(94.702,51.298) 94.724,51.298 v1@94.864,51.439 ; R18.1@95.313,45.343 95.338,45.343 96.385,44.296 96.478,44.296 97.178,43.596 97.178,42.325 96.986,42.134 96.294,42.134 95.81,41.65 92.767,41.65 92.071,40.954 ; v1(97.133,29.827) 97.185,29.827 97.787,29.225 C119.1@98.725,29.225 98.725,29.25 98.125,29.85 Q1.2@98.125,31.2 99.555,31.2 100.879,32.524 102.637,32.524 103.521,31.64 R13.1@105.652,31.64 ; R23.1@101.087,47.486 R19.1@101.087,49.391 ; R19.1@101.098,49.391 101.098,49.416 100.75,49.764 96.539,49.764 v1@94.864,51.439 ; 101.138,16.769 TP15.1@99.222,18.686 99.222,20.227 C25.1@99.247,20.253 99.272,20.253 101.257,22.238 101.257,23.158 U3.8@101.323,23.224 ; 101.167,16.868 101.263,16.773 102.223,15.813 102.223,14.55 R62.1@101.348,13.675 ; U3.8@101.323,23.524 v1(101.323,25.637) ; R13.1@105.652,31.589 R13.1@105.817,31.424 ; v1(106.157,20.155) 106.786,20.784 106.786,20.904 107.012,21.13 U4.5@107.012,21.194
  Bottom Layer w0.254: v1(82.3,51.155) 82.318,51.137 89.576,51.137 v1(91.372,49.341) 92.767,49.341 94.702,51.276 v1(94.702,51.298) ; J10.2@87.337,12.949 90.303,12.949 95.954,18.6 99.136,18.6 TP15.1@99.222,18.686 104.776,18.686 106.157,20.068 v1(106.157,20.155) ; v1(92.172,39.418) 96.251,35.339 96.251,30.709 v1(97.133,29.827) v1(101.323,25.637)
VCOIL: C124.+ C125.+ D1.K D2.K D6.+ D22.K K1.PLUS Q1.3 R20.2 R52.1 R56.1 R181.1 | length 127.5
  Top Layer w0.508: D1.K@86.847,43.526 86.847,44.366 K1.PLUS@88.743,46.262 88.743,45.858 89.542,45.059 89.542,43.642 D2.K@89.66,43.525 ; D22.K@89.743,34.44 D22.K@90.303,35 ; R181.1@90.56,36.821 90.339,36.601 90.339,35.036 D22.K@90.303,35 ; v1(94.196,26.286) 94.214,26.268 D6.+@95.304,26.268 ; Q1.3@97.175,33.8 97.175,33.6 96.814,33.24 94.196,33.24 93.975,33.461 93.714,33.461 C125.+@92.175,35 ; C124.+@103.669,35 101.277,37.392 98.541,37.392 97.568,36.419 93.593,36.419 C125.+@92.175,35 ; R56.1@109.68,76.835 R52.1@111.443,76.835 ; R52.1@111.468,76.835 R52.1@111.443,76.835 ; v1(112.679,76.85) 112.672,76.843 111.451,76.843 R52.1@111.443,76.835 ; D22.K@90.303,35 C125.+@92.175,35
  Bottom Layer w0.508: K1.PLUS@88.743,46.262 90.943,44.062 90.943,36.231 C125.+@92.175,35 94.196,32.979 v1(94.196,26.286) ; C124.+@103.669,35 103.669,32.782 111.649,24.802 113.453,24.802 115.25,26.599 115.25,34.932 111.221,38.961 111.221,75.392 v1(112.679,76.85)
VCP_PROBE2TGT: J11.5 J12.13 J15.7 J16.7 | length 98.9
  Top Layer w0.254: v1(132.886,73.106) 134,74.221 J15.7@134,77.75 ; v1(133.185,71) 131.298,69.113 131.298,64.447 132.192,63.553 133.835,63.553 J11.5@135,62.388 138.907,62.388 143.6,57.695 143.6,50.52 J12.13@142.27,49.19 ; J16.7@134,2.25 134,3.75 138.846,8.596 v1(138.846,8.6) ; v1(141.073,9.4) 140.927,9.254 140.927,8.646 140.665,8.384 140.665,6.085 140.895,5.855 141.786,5.855 142.5,6.569 142.5,45.354 v1(142.37,45.484)
  Bottom Layer w0.254: v1(132.886,73.106) 132.886,72.9 133.185,72.601 v1(133.185,71) ; v1(138.846,8.6) 139.646,9.4 v1(141.073,9.4) ; J12.13@142.27,49.19 141.454,48.374 141.454,46.302 142.272,45.484 v1(142.37,45.484)
VCP_TGT2PROBE: J11.17 J12.14 J15.8 J16.8 | length 94.4
  Top Layer w0.254: v1(131.104,53.662) 131.104,58.739 131.298,58.934 131.298,63.805 130.844,64.259 130.844,69.301 131.298,69.755 131.298,70.053 132.35,71.106 132.35,71.346 132.84,71.835 133.08,71.835 133.88,72.635 133.88,73.011 134.369,73.5 134.745,73.5 136,74.755 J15.8@136,77.75 ; J11.17@135,47.148 137.042,49.19 J12.14@141,49.19 ; J16.8@136,2.25 136,3.75 138.354,6.104 138.354,6.542 v1(138.5,6.688) ; v1(141.5,6.75) 141.5,6.872 141.908,7.28 141.908,43.036 141.781,43.163 141.781,43.936 v1(141.665,44.052)
  Bottom Layer w0.254: v1(131.104,53.662) 131.16,53.606 133.034,53.606 133.838,52.802 133.838,48.31 J11.17@135,47.148 ; v1(138.5,6.688) 138.531,6.719 141.469,6.719 v1(141.5,6.75) ; J12.14@141,49.19 141,44.717 v1(141.665,44.052)
VTref: J11.1 J12.3 J13.1 J15.10 J16.10 NT1.1 | length 104.2
  Top Layer w0.254: J13.1@133.538,15.328 134.7,14.166 137.052,14.166 ; J11.1@135,67.468 140,72.468 J15.10@140,77.75 ; J16.10@140,2.25 140,7.931 140.135,8.066 140.135,9.134 140,9.269 140,11.218 137.052,14.166 ; v1(142.864,47.223) 140.83,45.189 140.83,43.706 141,43.536 141,18.113 137.052,14.166
  Bottom Layer w0.254: NT1.1@120,15.275 122.7,15.275 123.25,14.726 125.7,14.726 126.25,15.275 133.485,15.275 J13.1@133.538,15.328 ; J11.1@135,67.468 143.127,59.341 143.127,56.145 142.935,55.953 142.901,55.953 142.488,55.54 J12.3@142.27,55.54 143.127,54.683 143.127,52.727 143.581,52.273 143.581,48.647 143.127,48.193 143.127,47.58 142.864,47.317 v1(142.864,47.223)
zero_cross: R30.2 U6.4 U7.17 ZC.1 | length 17.5
  Top Layer w0.254: U7.17@62.989,12.49 65.34,12.49 65.85,13 ZC.1@68,13 71.273,13 R30.2@71.285,13.012 71.285,13.052 70.035,14.301 U6.4@70.035,21.53
pads on no net: J11.2 J11.3 J11.11 J11.14 J11.16 J11.18 J11.20 J12.2 J12.9 J12.10 J12.11 J15.2 J15.5 J16.2 J16.5 MECH1.1 MECH1.2 MH2.1 MH3.1 MH4.1 MH5.1 P1.0 P1.6 U5.3 U5.5 U9.4

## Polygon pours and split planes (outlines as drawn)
GND_PROT on Bottom Layer "BOT_GNDPROT" (solid, pour order 4): 47,1.5 88.5,1.5 88.5,16.362 81.172,23.69 49.732,23.69 47,20.958
heater_out on Bottom Layer "BOT_HOUT" (solid, pour order 3): 14,1.5 14,28.075 39.325,28.075 39.401,28 41,28 41,1.5
NEUT on Bottom Layer "BOT_NEUT" (solid, pour order 1): 1.5,46 14.39,46 24.89,35.5 26.124,35.5 26.124,32.5 1.5,32.5
LINE on Bottom Layer "BOT_LINE" (solid, pour order 0): 1.5,50 1.5,58.75 12.5,58.75 16.25,55 24.45,55 33.2,46.25 48.369,46.25 65,62.881 65,78 95,78 95,70.5 84.067,70.5 75.717,62.15 75.717,38.967 73.75,37 27.717,37 14.717,50
GND on Top Layer "TOP_GND" (solid, pour order 5): 12.5,78.5 12.5,68.75 37.5,68.75 37.5,78.5
L2 on Top Layer "TOP_L2" (solid, pour order 2): 62.5,67.5 62.5,61.147 55.15,53.797 44.005,53.797 20.208,30 1.5,30 1.5,12 18,12 43.5,37.5 68.025,37.5 73.25,42.725 73.25,67.5

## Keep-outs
Keep-Out Layer:
  lines w1.016: 124,10 119,10 ccw(c119,5) 114,5 114,0 10,0 10,5 ccw(c5,5) 5,10 0,10 0,70 5,70 ccw(c5,75) 10,75 10,80 114,80 114,75 ccw(c119,75) 119,70 124,70

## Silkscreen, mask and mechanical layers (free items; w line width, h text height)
Top Overlay:
  rectangle: 32.776,36.631 47.381,44.886
  region: 75.788,27.955 74.518,28.59 74.518,27.32
  region: 96.522,60.73 97.157,62 95.887,62
  region: 108.735,37.512 110.005,36.877 110.005,38.147
  region: 119.464,20.344 118.194,20.979 118.194,19.709
  region: 75.4,45.373 76.035,46.643 74.765,46.643
  region: 83.285,35.95 82.65,34.68 83.92,34.68
  region: 90.637,43.513 91.907,42.878 91.907,44.148
  region: 85.783,43.479 84.513,44.114 84.513,42.844
  region: 108.735,43.973 110.005,43.338 110.005,44.608
  region: 92.378,32.902 91.743,31.632 93.013,31.632
  region: 83.488,28.885 82.853,27.615 84.123,27.615
  region: 117.865,29.542 119.135,28.907 119.135,30.177
  region: 109.391,27.318 110.661,26.682 110.661,27.953
  lines w0.152: 78.098,41.704 79.102,42.707 79.222,42.707 ; 85.088,54.25 85.75,54.912 85.75,57.25
  lines w0.2: 134.998,5 134.998,7.458 ; 135,72.577 135,75
  lines w0.254: 74.765,45.373 76.035,45.373 ; 75.788,27.32 75.788,28.59 ; 82.65,35.95 83.92,35.95 ; 82.853,28.885 84.123,28.885 ; 85.783,42.844 85.783,44.114 ; 90.637,42.878 90.637,44.148 ; 91.743,32.902 93.013,32.902 ; 95.887,60.73 97.157,60.73 ; 108.735,36.877 108.735,38.147 ; 108.735,43.338 108.735,44.608 ; 109.391,26.683 109.391,27.953 ; 117.865,28.907 117.865,30.177 ; 119.464,19.709 119.464,20.979 ; 16.734,36.661 28.926,36.661 28.926,44.789 16.734,44.789 16.734,36.661
  text "LC Charger Stabilizer" at 3.167,66.25 h1.52
  text "Licensed under CERN-OHL-P v2" at 3.305,63.25 h1.52
  text "Source package at https://docs.2to8.cc" at 3.305,60.25 h1.52
  text "Revision" at 16.734,45.805 h1.52
  text "Serial #" at 34.3,45.775 h1.52
  text ".nhProjRev" at 19.558,39.735 h3.05
  text "High Thresh" at 114.023,34.549 h0.9
  text "Sense Prot" at 114.247,30.445 h0.9
  text "HV     to GND   : 4.0mm (0.158\")" at 11.78,10.81 h1.78
  text "LINEin to NEUT  : 3.0mm (0.120\")" at 11.78,9.54 h1.78
  text "LINE to LINEPROT: 3.0mm (0.120\")" at 11.78,8.27 h1.78
  text "NEUT to LINEPROT: 1.5mm (0.060\")" at 11.78,7 h1.78
Bottom Overlay:
  rectangle: 99.645,5.996 114.25,14.251
  lines w0.127: 103.309,37.6 122.309,37.6 122.309,69.2 103.383,69.2 103.383,37.674
  lines w0.2: 134.998,5 134.998,7.458 ; 135,72.75 135,75
  lines w0.254: 105.589,71.743 104.302,72.193 ; 105.589,72.686 104.302,72.193 ; 106.842,72.193 104.302,72.193 ; 63.843,38.119 76.035,38.119 76.035,46.247 63.843,46.247 63.843,38.119
  lines w0.406: 91.407,27.2 93.185,27.2 ; 91.407,27.9 93.185,27.9 ; 102.763,27.2 104.541,27.2 ; 102.763,27.9 104.541,27.9
  lines w0.5: 8.694,74.797 9.492,73.5 11,73.5 ; 10.2,74.8 11,73.5 ; 11,71 11,73.5 ; 11.722,74.814 12.531,73.5 11,73.5 ; 18.694,74.797 19.492,73.5 21,73.5 ; 20.2,74.8 21,73.5 ; 21,71 21,73.5 ; 21.722,74.814 22.531,73.5 21,73.5 ; 28.694,74.797 29.492,73.5 31,73.5 ; 30.2,74.8 31,73.5 ; 31,71 31,73.5 ; 31.722,74.814 32.531,73.5 31,73.5
  lines w0.6: 127.701,32.64 129.031,32.64 ; 135,32.5 136.078,32.5 ; 141.915,32.5 144.25,32.5
  text "voltage" at 103.249,77.444 h2.03 r180
  text "over" at 103.249,74.774 h2.03 r180
  text "ARM20" at 140.924,71.483 h1.27 r90
  text "Probe" at 142.912,71.389 h1.27 r90
  text "Ground" at 26.69,68.967 h2.03 r180
  text "Earth" at 16.421,68.916 h2.03 r180
  text "Line In" at 2,60 h2.03 r180
  text "Neutral In" at 1.104,49.486 h2.03 r180
  text "STDC14" at 141.878,47.162 h1.27 r90
  text ".nhProjRev" at 70.205,43.508 h3.05 r180
  text "Fan Neutral" at 2.104,40.486 h2.03 r180
  text "5V from probe" at 141.173,39.05 h1.27 r90
  text "Revision" at 65.895,37.142 h1.52 r180
  text "HighThresh" at 113.95,35.604 h1.27 r180
  text "nRESET" at 134.362,35.429 h1.27 r90
  text "Fan Line" at 2.177,31.007 h2.03 r180
  text "Sense Prot" at 113.95,30.434 h1.27 r180
  text "Source package at https://docs.2to8.cc" at 42.904,28.712 h1.52 r180
  text "Licensed under CERN-OHL-P v2" at 42.904,26.712 h1.52 r180
  text "Low Thresh" at 113.95,26.508 h1.27 r180
  text "LC Charger Stabilizer" at 42.904,24.69 h1.52 r180
  text "T_ON" at 60.714,21.013 h1 r180
  text "TC2030" at 142.104,20.419 h1.27 r90
  text "Prot" at 95.612,20.385 h1.27 r180
  text "Target" at 143.712,19.965 h1.27 r90
  text "Heater L" at 1.637,19.911 h2.03 r180
  text "for prog." at 84.654,18.835 h1 r180
  text "Prot" at 113.009,18.821 h1.27 r180
  text "Vcc" at 95.412,18.135 h1.27 r180
  text "GND" at 113.009,17.043 h1.27 r180
  text "PB6" at 66.23,16.53 h1 r180
  text "PC14" at 48.666,16.376 h1 r180
  text "-" at 91.71,16.298 h1 r180
  text "PC15" at 48.82,14.286 h1 r180
  text "ZC" at 68.987,13.969 h1
  text "+5->9V" at 91.77,13.457 h1 r180
  text "PA11" at 69.275,11.456 h1 r180
  text "PA0" at 45.008,9.561 h1 r180
  text "SNS" at 77.391,9.424 h1 r180
  text "PA7" at 69.029,9.311 h1 r180
  text "PA1" at 47.904,7.596 h1 r180
  text "PA6" at 69.029,7.5 h1 r180
  text "PA2" at 51.323,5.846 h1 r180
  text "PA5" at 66.904,5.75 h1 r180
  text "Heater SW" at 25.737,5.007 h2.03 r180
  text "PA3" at 54.393,5.004 h1 r180
  text "PA4" at 63.23,4.596 h1 r180
  text "Serial #" at 103.5,4.565 h1.52 r180
  text "NRST_MCU" at 59.912,2.513 h1 r180
Board Outline:
  lines w0.1: 97.354,74.117 99.504,74.117 99.504,76.467 97.354,76.467 97.354,74.117
  lines w0.508: 0,0 124,0 124,10 cw(c126,10) 128,10 128,0 145,0 145,80 128,80 128,70 cw(c126,70) 124,70 124,80 0,80 0,0
  lines w1.6: 125,21.534 125,60.75
User Drawing:
  circle w0.102: c46.75,50.248 r3.9
  circle w0.102: c34.664,50.086 r3.9
  circle w0.102: c8.54,45 r5
  circle w0.102: c102.824,64.047 r3.889
  circle w0.102: c117.2,63.519 r3
  circle w0.102: c117.328,62.222 r3
  circle w0.102: c119.5,27.799 r3
  circle w0.102: c90.013,20.269 r3.048
  circle w0.102: c17.087,57.588 r2.35
  circle w0.102: c47,67.002 r2.35
  circle w0.102: c53.4,57.75 r3.912
  circle w0.102: c47,77 r8.8
  circle w0.102: c22.587,50.086 r2.35
  circle w0.102: c8.54,55 r5
  circle w0.102: c56.832,67.067 r3.8
  circle w0.102: c56.832,77.067 r3.81
  circle w0.102: c29.164,57.586 r2.35
  circle w0.102: c58.9,50.25 r3.912
  circle w0.102: c92.493,71.602 r4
